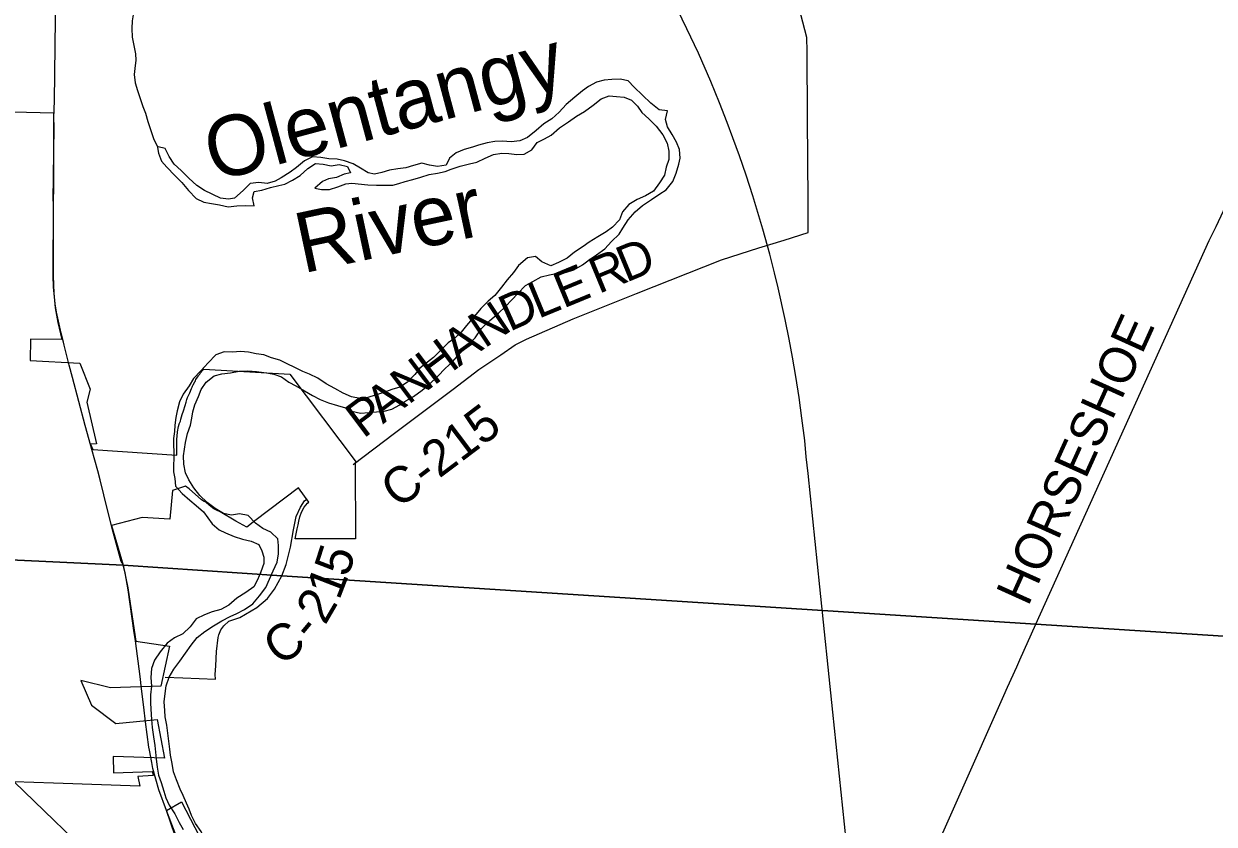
# Model space of a CAD drawing. Extents: x 1674899 to 2057726, y 653888 to 988278.
# Drawn here: x 1808187 to 1818064, y 846092 to 852735 of the extents above; entities that cross this region are included whole.
import ezdxf

# ---------------------------------------------------------------- set-up
doc = ezdxf.new("R2010")
doc.units = 0
for name, color, linetype in [('GM_X_Corporation', 7, 'Continuous'), ('GM_X_County_Road', 7, 'Continuous'), ('GM_X_County_Road_Text', 7, 'Continuous'), ('GM_X_Major_River', 7, 'Continuous'), ('GM_X_Major_River_Text', 7, 'Continuous'), ('GM_X_Rail_Line', 7, 'Continuous'), ('GM_X_Township', 7, 'Continuous'), ('GM_X_US_Route', 7, 'Continuous'), ('SH_Data', 7, 'Continuous')]:
    doc.layers.add(name, color=color, linetype=linetype)

msp = doc.modelspace()

# ---------------------------------------------------------------- linework, layer by layer
at = {"layer": 'GM_X_Corporation'}
for points in [[(1807090.5, 852030.9), (1808433.3, 851997.1), (1808430.6, 850641.2), (1808435.6, 850498.4), (1808448.8, 850376.5), (1808470.4, 850254.7), (1808503.7, 850114.3), (1808242.6, 850117.7), (1808241.4, 849940.9), (1808653.6, 849917.4), (1808736.6, 849703.2), (1808709.5, 849594.5), (1808789.7, 849247.5), (1808740.4, 849246), (1808759.2, 849201.3), (1809456.4, 849153.7), (1809458.3, 849293.9), (1809458.8, 849306.9), (1809459.7, 849321.9), (1809461.3, 849339.8), (1809462.4, 849348.8), (1809462.7, 849349.8), (1809464.3, 849361.6), (1809467.4, 849379.4), (1809470.4, 849393.1), (1809472.4, 849400.8), (1809474.7, 849407.4), (1809476, 849410.7), (1809477.3, 849413.9), (1809480.2, 849420.4), (1809484.2, 849430.6), (1809486.2, 849436.3), (1809491.3, 849453.5), (1809496.8, 849473.8), (1809501.8, 849491.1), (1809511.4, 849521.6), (1809526.6, 849568.1), (1809534.3, 849594.8), (1809537.1, 849604.6), (1809541.3, 849618), (1809544.1, 849626.5), (1809546.1, 849632.1), (1809551.1, 849644.1), (1809559.7, 849662.2), (1809564.6, 849673.2), (1809578.4, 849707.6), (1809583.4, 849719.5), (1809587.6, 849728.6), (1809592.6, 849738.4), (1809606.4, 849763.9), (1809610.9, 849772.8), (1809615.5, 849781.8), (1809621.5, 849792.1), (1809623.1, 849794.6), (1809627.8, 849801.1), (1809636.7, 849812), (1809640.8, 849817.6), (1809646.6, 849825.9), (1809654.2, 849837.6), (1809659.5, 849844.8), (1809665.8, 849852.5), (1809681.3, 849869.6), (1810394.1, 849826.1), (1810944.6, 849097.3), (1810937.2, 849091.7), (1810938.9, 848461.5), (1810439.8, 848460.4), (1810456.3, 848543.1), (1810462.5, 848575.2), (1810468.8, 848607.4), (1810478.5, 848644.1), (1810492.1, 848681.9), (1810514.7, 848723), (1810542, 848756.1), (1810551.8, 848765.3), (1810465.5, 848882.7), (1810104.8, 848611.1), (1810038.5, 848558), (1809945.3, 848607.5), (1809816.7, 848685.3), (1809792.1, 848696.4), (1809763.1, 848710.7), (1809725.8, 848739.6), (1809696.6, 848763.7), (1809685, 848771.5), (1809661.7, 848785.4), (1809559.7, 848874.9), (1809530, 848898.8), (1809421.3, 848861.3), (1809398.5, 848624.8), (1809168.2, 848636.6), (1808913.8, 848570.5), (1809012, 848240.9), (1809051.8, 848052.7), (1809116.6, 847609.9), (1809395.4, 847570.7), (1809324.5, 847237.2), (1808905.8, 847222.5), (1808660.3, 847283.7), (1808750.4, 847078.8), (1808949.9, 846926.5), (1809293.9, 846960.7), (1809355.4, 846639.4), (1808927.8, 846653.4), (1808932.6, 846517.5), (1809251.4, 846528.7), (1809259.5, 846495.6), (1809133.3, 846486.7), (1809148.8, 846407.2), (1808433.2, 846432.2), (1808107.2, 846443.6), (1808850, 845723.9)], [(1809452.7, 845995.8), (1809370.2, 846204.8), (1809494.6, 846276.2), (1809904.5, 845489.7)]]:
    msp.add_lwpolyline(points, dxfattribs=at)
at = {"layer": 'GM_X_County_Road'}
for points in [[(1816452.3, 847455.2), (1816585.7, 847751.3), (1818021.5, 850936.9), (1818080.6, 851051.6), (1818426.4, 851790.7), (1818462.5, 851866.6), (1818600.4, 852026.5), (1818666.6, 852103.2), (1818835.2, 852306.4), (1818894.6, 852378), (1819166, 852831), (1819204.7, 852895.5), (1819487.3, 853403), (1819530.7, 853481.1), (1819699.4, 854255), (1819714.7, 854325.4), (1819939.9, 855786.8), (1819970.6, 855999.9), (1819978.5, 856052.5)], [(1814694.4, 851004.4), (1814694.7, 851266), (1814689.4, 851949.7), (1814688.5, 852505.2), (1814683.1, 852620.4), (1814443.9, 853546.9), (1814428.6, 853618.3), (1814334.6, 854030.1), (1814320.5, 854091.6), (1814317.2, 854102.3)], [(1810919.1, 849077.6), (1811262.7, 849337), (1811751, 849701.5), (1811961.5, 849865), (1812146.5, 849988.4), (1812263.7, 850069.4), (1812359.1, 850118.6), (1812745.4, 850286.5), (1813270.8, 850497.8), (1813977.4, 850776.9), (1814285.7, 850876.9), (1814495.2, 850939.2), (1814694.4, 851004.4)], [(1809806.6, 847662.7), (1809821.3, 847703.6), (1809846.5, 847738.8), (1809889.3, 847776.6), (1809980.5, 847807.3), (1810120.4, 847889.7), (1810210.6, 847966.4), (1810266.1, 848041.2), (1810327.5, 848152), (1810364.3, 848246.6), (1810399.3, 848390.4), (1810424.5, 848536.1), (1810447.8, 848646.8), (1810482.8, 848724.5), (1810515.8, 848776.9), (1810538.1, 848793.3)], [(1809360.2, 847312.3), (1809507.8, 847307.8), (1809776.7, 847295.3), (1809775.2, 847335.4), (1809780.8, 847406.2), (1809787.5, 847525.8), (1809798.7, 847640.7), (1809806.6, 847662.7)], [(1814100.7, 842163.9), (1814760.4, 843649.3), (1815210.3, 844662.2), (1816319.7, 847160.1), (1816350.6, 847229.4), (1816426.4, 847397.7), (1816452.3, 847455.2)]]:
    msp.add_lwpolyline(points, dxfattribs=at)
at = {"layer": 'GM_X_Major_River'}
for points in [[(1809101.6, 852887.5), (1809097.5, 852877.5), (1809097.1, 852827.5), (1809086.6, 852759.4), (1809084, 852695.4), (1809085.5, 852625.3), (1809098.9, 852555.1), (1809114.4, 852486.9), (1809117.9, 852432.8), (1809109.4, 852364.7), (1809103, 852314.7), (1809110.4, 852246.6), (1809131.9, 852182.3), (1809174.8, 852049.8), (1809198.4, 851993.5), (1809217.8, 851923.3), (1809241.2, 851851), (1809262.7, 851782.8), (1809296.1, 851714.4)], [(1812126.9, 850332.7), (1812185.3, 850388.3), (1812235.8, 850444), (1812286.2, 850495.7), (1812348.7, 850563.3), (1812411, 850596.9), (1812481.3, 850634.4), (1812549.4, 850651.9), (1812615.5, 850665.4), (1812689.6, 850674.8), (1812749.8, 850692.4), (1812822.1, 850733.9), (1812888.5, 850783.4), (1812938.8, 850817.1), (1813009.2, 850866.7), (1813063.7, 850928.3), (1813126.1, 850987.9), (1813156.5, 851039.8), (1813203.1, 851107.5), (1813259.6, 851175.2), (1813322.1, 851226.7), (1813394.5, 851278.3), (1813464.8, 851323.8), (1813517.1, 851357.4), (1813573.7, 851427.1), (1813600.2, 851495), (1813622.8, 851568.9), (1813633.2, 851620.9), (1813627.8, 851691), (1813602.3, 851753.3), (1813566.8, 851815.7), (1813527.3, 851880.1), (1813511.8, 851942.3), (1813528.4, 852014.2), (1813458.5, 852020.8), (1813388.9, 852077.4), (1813319.5, 852144), (1813252, 852210.7), (1813202.4, 852261.1), (1813134.5, 852275.6), (1813066.5, 852274.2), (1813002.5, 852268.7), (1812938.3, 852251.1), (1812872, 852213.6), (1812821.8, 852179.9), (1812759.3, 852126.3), (1812686.9, 852064.8), (1812630.4, 852003.2), (1812567.9, 851947.5), (1812501.6, 851906), (1812439.1, 851848.4), (1812366.7, 851792.9), (1812302.4, 851763.3), (1812232.4, 851755.8), (1812158.4, 851760.4), (1812094.4, 851758.9), (1812032.3, 851747.4), (1811960.2, 851727.9), (1811910, 851712.3), (1811839.9, 851690.8), (1811775.7, 851665.2), (1811719.3, 851619.6), (1811690.8, 851561.8), (1811620.7, 851550.3), (1811554.8, 851560.8), (1811491, 851579.3), (1811420.8, 851557.8), (1811356.7, 851540.3), (1811290.6, 851532.8), (1811222.5, 851521.3), (1811158.3, 851501.8), (1811096.2, 851486.2), (1811044.3, 851498.6), (1810980.6, 851537.2), (1810920.9, 851571.7), (1810849.1, 851598.3), (1810787.3, 851612.8), (1810719.3, 851615.3), (1810651.4, 851625.8), (1810583.4, 851630.4), (1810515.1, 851596.8), (1810448.7, 851541.3), (1810398.4, 851503.6), (1810322, 851456.1), (1810271.8, 851428.5), (1810205.6, 851409), (1810137.7, 851417.5), (1810065.6, 851410.1), (1810007.2, 851352.4), (1809936.7, 851288.9), (1809886.6, 851279.3), (1809818.7, 851287.8), (1809687.2, 851352.9), (1809623.5, 851393.4), (1809558, 851454), (1809492.5, 851516.6), (1809434.9, 851569.1), (1809393.4, 851633.5), (1809360, 851699.9), (1809301.3, 851713.5), (1809296.1, 851714.4)], [(1809296.1, 851714.4), (1809295.6, 851709.9), (1809303.7, 851660.3), (1809331.1, 851596), (1809374.7, 851545.6), (1809440.2, 851477), (1809499.7, 851418.4), (1809555.2, 851351.9), (1809618.6, 851285.3), (1809682.4, 851254.8), (1809744.3, 851244.3), (1809812.2, 851231.8), (1809884.1, 851217.2), (1809954.1, 851224.7), (1810026.2, 851228.1), (1810098.1, 851223.5), (1810084.7, 851291.8), (1810099.1, 851343.7), (1810163.2, 851355.2), (1810235.4, 851376.7), (1810303.5, 851394.2), (1810353.6, 851403.8), (1810415.9, 851437.4), (1810480.2, 851474.9), (1810544.6, 851534.5), (1810607, 851576.1), (1810670.9, 851569.6), (1810736.8, 851555.1), (1810804.9, 851566.6), (1810872.8, 851552), (1810898.3, 851497.8), (1810846.2, 851486.2), (1810782, 851458.6), (1810715.9, 851449.1), (1810665.8, 851427.4), (1810603.3, 851369.9), (1810657.2, 851359.4), (1810723.2, 851360.9), (1810793.4, 851382.4), (1810859.6, 851405.9), (1810909.6, 851411.5), (1811041.5, 851398.5), (1811113.5, 851396), (1811179.5, 851395.5), (1811249.5, 851394.9), (1811299.6, 851410.5), (1811351.7, 851426.2), (1811415.9, 851443.7), (1811482, 851461.2), (1811550.2, 851484.7), (1811620.3, 851496.2), (1811682.4, 851509.7), (1811732.5, 851527.4), (1811806.7, 851552.8), (1811884.9, 851572.3), (1811947, 851587.8), (1812015.3, 851621.3), (1812085.5, 851650.8), (1812153.6, 851660.3), (1812211.6, 851659.9), (1812279.5, 851651.3), (1812339.5, 851652.9), (1812401.8, 851690.5), (1812446.3, 851750.2), (1812506.6, 851781.8), (1812562.8, 851811.4), (1812631.3, 851873), (1812707.7, 851920.4), (1812772.1, 851968), (1812840.4, 852007.5), (1812910.8, 852061.1), (1812977.2, 852112.6), (1813043.4, 852136.2), (1813105.4, 852131.7), (1813169.3, 852127.2), (1813229.1, 852100.7), (1813280.7, 852052.2), (1813314.3, 851999.9), (1813373.9, 851947.3), (1813433.4, 851884.8), (1813488.8, 851814.3), (1813526.2, 851745.9), (1813539.7, 851677.7), (1813539.1, 851609.6), (1813518.6, 851545.7), (1813504.1, 851477.7), (1813461.6, 851415.9), (1813413, 851346.2), (1813346.7, 851308.7), (1813276.5, 851277.2), (1813206.1, 851235.6), (1813155.7, 851175.9), (1813129.1, 851108.1), (1813070.6, 851046.4), (1813018.3, 851008.8), (1812950, 850967.2), (1812877.6, 850923.7), (1812827.3, 850886.1), (1812756.9, 850838.5), (1812694.5, 850788.9), (1812624.3, 850755.4)], [(1812624.3, 850755.4), (1812560, 850725.9), (1812486.3, 850760.5), (1812432.7, 850803), (1812366.6, 850793.5), (1812292.1, 850730), (1812251.6, 850670.2), (1812197.1, 850610.5), (1812150.6, 850548.8), (1812096.1, 850481.1), (1812039.7, 850433.5), (1811979.2, 850371.9), (1811926.7, 850308.2), (1811860.1, 850230.6), (1811817.6, 850176.8), (1811761.2, 850123.2), (1811708.9, 850087.5), (1811652.5, 850031.9), (1811587.9, 849964.3), (1811535.6, 849926.7), (1811473.2, 849877.1), (1811432.8, 849825.3), (1811372.3, 849761.7), (1811308, 849718.1), (1811239.8, 849700.6), (1811167.6, 849673.1), (1811101.4, 849653.6), (1811041.3, 849634), (1810979.2, 849626.5), (1810907.3, 849639.1), (1810837.6, 849669.7), (1810767.9, 849708.3), (1810696.2, 849746.9), (1810626.6, 849793.5), (1810556.9, 849828.1), (1810503, 849850.5), (1810437.3, 849883.1), (1810373.5, 849911.6), (1810311.8, 849942.1), (1810243.9, 849962.7), (1810178.2, 849987.2), (1810114.2, 849995.7), (1810052.3, 850010.2), (1809984.4, 850014.8), (1809918.3, 850009.2), (1809850.4, 850013.8), (1809780.2, 849988.3), (1809717.6, 849920.7), (1809657.1, 849855), (1809596.6, 849791.4), (1809558.1, 849731.6), (1809509.5, 849661.9), (1809479, 849598.1), (1809460.4, 849524.1), (1809448, 849468.1), (1809441.5, 849404.1), (1809439, 849352), (1809428.6, 849292), (1809430.1, 849239.9), (1809431.7, 849183.8), (1809430.3, 849015.6), (1809439.9, 848961.5), (1809445.4, 848897.3), (1809500.9, 848836.8), (1809564.5, 848780.2), (1809616.1, 848735.8), (1809679.7, 848685.2), (1809750.9, 848584.5), (1809808.5, 848536), (1809860.3, 848509.6), (1809932, 848481), (1810001.9, 848456.4), (1810073.7, 848441.8), (1810137.5, 848413.3), (1810163.1, 848361), (1810178.6, 848306.8), (1810178.2, 848254.8), (1810153.7, 848186.8), (1810125.1, 848119), (1810094.7, 848063.1), (1810028.3, 848015.6), (1809953.9, 847968.1), (1809887.5, 847908.5), (1809823.2, 847872.9), (1809751, 847855.5), (1809686.8, 847829.9), (1809618.6, 847796.4), (1809568, 847728.7), (1809505.6, 847673.1), (1809437.3, 847639.6), (1809377, 847594), (1809318.4, 847522.3), (1809271.8, 847452.6), (1809247.3, 847382.7), (1809240.7, 847310.6), (1809248.1, 847238.5), (1809239.5, 847166.4), (1809239, 847098.3), (1809240.6, 847046.2), (1809245.9, 846960.1), (1809253.4, 846893.9)], [(1809611, 846097.9), (1809579.6, 846164.3), (1809560, 846216.5), (1809536.4, 846266.8), (1809508.9, 846331.1), (1809485.3, 846383.3), (1809453.9, 846459.7), (1809430.4, 846526), (1809417, 846596.2), (1809405.5, 846664.4), (1809397.9, 846714.5), (1809383, 846846.8), (1809373.5, 846913), (1809360.1, 846983.2), (1809356.5, 847035.3), (1809351.1, 847107.5), (1809359.6, 847175.5), (1809368.1, 847239.5), (1809392.7, 847311.4), (1809431.2, 847377.2), (1809481.8, 847444.9), (1809530.3, 847510.7), (1809576.8, 847576.4), (1809625.3, 847642.1), (1809689.7, 847691.7), (1809760.1, 847737.2), (1809830.4, 847780.8), (1809900.7, 847816.2), (1809954.9, 847841.9), (1810017.2, 847873.4), (1810087.6, 847921), (1810144.1, 847986.6), (1810194.6, 848056.3), (1810225.2, 848124.2), (1810255.7, 848194.1), (1810288.3, 848267.9), (1810300.9, 848335.9), (1810301.4, 848406), (1810293.9, 848460.2), (1810236.3, 848516.7), (1810170.6, 848547.2), (1810110.9, 848589.8), (1810049.4, 848654.3), (1809977.5, 848666.9), (1809911.4, 848655.4), (1809845.6, 848669.9), (1809775.9, 848712.5), (1809708.3, 848763.1), (1809648.8, 848819.7), (1809597.3, 848884.1), (1809555.8, 848950.5), (1809530.3, 849006.8), (1809514.9, 849079), (1809513.4, 849149.2), (1809519.9, 849205.2), (1809530.3, 849261.2), (1809546.9, 849335.2), (1809569.5, 849403.1), (1809581.9, 849463.1), (1809590.4, 849515.1), (1809606.8, 849573), (1809637.4, 849642.9), (1809659.8, 849698.8), (1809700.3, 849760.6), (1809766.8, 849814.1), (1809830.9, 849829.7), (1809903, 849839.1), (1809975.1, 849852.6), (1810047.1, 849856), (1810119, 849849.5), (1810201, 849838.8), (1810260.9, 849826.3), (1810326.7, 849805.8), (1810386.3, 849761.3), (1810444.1, 849730.8), (1810515.7, 849688.2), (1810581.4, 849649.6), (1810647.2, 849617.1), (1810714.9, 849588.5), (1810788.8, 849567.9), (1810856.6, 849547.4), (1810908.4, 849520.9), (1810982.2, 849504.3), (1811050.3, 849507.8), (1811114.3, 849513.3), (1811176.4, 849518.9), (1811240.5, 849536.4), (1811306.8, 849571.9), (1811357, 849605.6), (1811421.3, 849643.1), (1811491.8, 849694.7), (1811552.1, 849742.3), (1811622.7, 849809.8), (1811683.2, 849875.4), (1811745.6, 849929), (1811802.2, 849996.7), (1811862.7, 850060.3), (1811931.3, 850129.9), (1811983.9, 850205.6), (1812054.4, 850273.2), (1812126.9, 850332.7)], [(1809253.4, 846893.9), (1809264.8, 846815.7), (1809274.2, 846743.5), (1809285.3, 846635.3), (1809294.8, 846565.1), (1809304.2, 846498.9), (1809325.7, 846436.7), (1809349.2, 846366.4), (1809366.7, 846310.2), (1809394.2, 846249.8), (1809439.7, 846177.4), (1809477.1, 846107), (1809510.6, 846046.7)], [(1810152.2, 844729.7), (1810130.7, 844799.9), (1810115.4, 844878.2), (1810101.8, 844932.4), (1810076.3, 845002.7), (1810048.9, 845069), (1810031.3, 845123.2), (1810013.9, 845195.5), (1810000.3, 845247.6), (1809988.7, 845297.8), (1809977.1, 845350), (1809967.7, 845424.2), (1809962.1, 845478.3), (1809940.6, 845544.6), (1809907.2, 845614.9), (1809861.7, 845675.4), (1809804.2, 845739.9), (1809768.6, 845790.3), (1809735.1, 845858.6), (1809713.5, 845908.9), (1809690, 845961.1), (1809658.5, 846031.5), (1809611, 846097.9)]]:
    msp.add_lwpolyline(points, dxfattribs=at)
at = {"layer": 'GM_X_Rail_Line'}
msp.add_lwpolyline([(1815024.3, 845825.8), (1814900, 847022.3), (1814792.8, 848062.2), (1814694.8, 849003.1), (1814679.6, 849140.1), (1814666.5, 849276.5), (1814642.8, 849460.9), (1814619.5, 849632.7), (1814592.7, 849806.6), (1814564.9, 849967.3), (1814536.6, 850116.8), (1814503.3, 850282.1), (1814445.7, 850543.8), (1814415.4, 850667.6), (1814376, 850823.7), (1814318.3, 851031.4), (1814278.4, 851168.4), (1814235.5, 851307.8), (1814180.4, 851477.6), (1814124.8, 851639.3), (1814071.3, 851788.9), (1814023.2, 851916.2), (1813959.6, 852078.9), (1813886.8, 852257.3), (1813784.2, 852491.3), (1813688.7, 852694.9), (1813610.9, 852854.1)], dxfattribs=at)
at = {"layer": 'GM_X_Township'}
msp.add_lwpolyline([(1794528.5, 849264.7), (1794738.4, 851729.1), (1795089.6, 856488.1), (1795246.9, 858498.9), (1795572.8, 862604.1), (1796250.1, 870608.5), (1796650.9, 875449.1), (1801483.5, 875120.1), (1808583.7, 874680.4), (1818820.4, 874127.4), (1822582.6, 873900.6), (1822382.4, 871012.6), (1821955.8, 864281.1), (1821820, 862137.7), (1821742.6, 860915.1), (1821306.3, 853784), (1821203.9, 851968.5), (1820950.3, 847471.9), (1816585.7, 847751.2), (1810327.5, 848152), (1809012, 848240.9), (1805038.1, 848429.5), (1801113.4, 848727.8), (1800736.4, 848740)], close=True, dxfattribs=at)
msp.add_lwpolyline([(1805038.1, 848429.5), (1809012, 848240.9), (1810327.5, 848152), (1816585.7, 847751.2), (1820950.3, 847471.9), (1820789.2, 844649.9), (1820410.6, 838018.1), (1820357.1, 837080.2), (1820273.9, 835622.7), (1820182.4, 834020.7), (1820000.3, 830811.8), (1819973.4, 830336.5), (1819571.4, 823252.9), (1819402.7, 820561.6), (1817422, 820661), (1816436.6, 820719.4), (1811976.8, 820983.9), (1811438.7, 820997.6), (1810371.4, 821058.5), (1808814, 821112.9), (1806011.6, 821223.2)], dxfattribs=at)
at = {"layer": 'GM_X_US_Route'}
for points in [[(1808436.7, 851953.6), (1808441.2, 852096.6), (1808473.9, 854817), (1808492.7, 856391.6), (1808500.9, 857013.5), (1808509.5, 857555.2), (1808510.5, 857627.6)], [(1808515.9, 850092.2), (1808496.1, 850167.3), (1808458.7, 850340.7), (1808447.9, 850410.8), (1808433.9, 850552), (1808430.6, 850641.2), (1808432.6, 851249.2), (1808431.5, 851273.4), (1808433.2, 851468.5), (1808436.7, 851667.7), (1808439.2, 851882.5), (1808436.7, 851953.6)], [(1808563.1, 849901.2), (1808563.1, 849901.2), (1808522.2, 850068.4), (1808515.9, 850092.2)], [(1808697.2, 849401.4), (1808591.8, 849800.4), (1808563.1, 849901.2)], [(1808752, 849201.8), (1808702.6, 849380.8), (1808697.2, 849401.4)], [(1808820.8, 848950.2), (1808802.8, 849023.6), (1808752, 849201.8)], [(1808920.8, 848545), (1808913.8, 848570.5), (1808882, 848700.2), (1808820.8, 848950.2)], [(1809104.2, 847680.7), (1809054.1, 848035.9), (1809027.1, 848178.7), (1809012, 848240.9), (1809010.4, 848249), (1808995, 848272.1), (1808920.8, 848545)], [(1809163.9, 847216.4), (1809151.8, 847318.6), (1809113.8, 847612.6), (1809104.2, 847680.7)], [(1809182.2, 847063.1), (1809163.9, 847216.4)], [(1809229.5, 846706.2), (1809224.6, 846732), (1809196.6, 846941.2), (1809182.2, 847063.1)], [(1809248.9, 846605.1), (1809229.5, 846706.2)], [(1809258.5, 846554.6), (1809248.9, 846605.1)], [(1809486.2, 845871.7), (1809442.3, 845994.9), (1809370.2, 846204.8), (1809307.3, 846377.8), (1809258.9, 846552.8), (1809258.5, 846554.6)]]:
    msp.add_lwpolyline(points, dxfattribs=at)
at = {"layer": 'SH_Data'}
for points in [[(1808436.7, 851953.6), (1808441.2, 852096.6), (1808473.9, 854817), (1808492.7, 856391.6), (1808500.9, 857013.5), (1808509.5, 857555.2), (1808510.5, 857627.6)], [(1808515.9, 850092.2), (1808496.1, 850167.3), (1808458.7, 850340.7), (1808447.9, 850410.8), (1808433.9, 850552), (1808430.6, 850641.2), (1808432.6, 851249.2), (1808431.5, 851273.4), (1808433.2, 851468.5), (1808436.7, 851667.7), (1808439.2, 851882.5), (1808436.7, 851953.6)], [(1808563.1, 849901.2), (1808563.1, 849901.2), (1808522.2, 850068.4), (1808515.9, 850092.2)], [(1808697.2, 849401.4), (1808591.8, 849800.4), (1808563.1, 849901.2)], [(1808752, 849201.8), (1808702.6, 849380.8), (1808697.2, 849401.4)], [(1808820.8, 848950.2), (1808802.8, 849023.6), (1808752, 849201.8)], [(1808920.8, 848545), (1808913.8, 848570.5), (1808882, 848700.2), (1808820.8, 848950.2)], [(1809104.2, 847680.7), (1809054.1, 848035.9), (1809027.1, 848178.7), (1809012, 848240.9), (1809010.4, 848249), (1808995, 848272.1), (1808920.8, 848545)], [(1809163.9, 847216.4), (1809151.8, 847318.6), (1809113.8, 847612.6), (1809104.2, 847680.7)], [(1809182.2, 847063.1), (1809163.9, 847216.4)], [(1809229.5, 846706.2), (1809224.6, 846732), (1809196.6, 846941.2), (1809182.2, 847063.1)], [(1809248.9, 846605.1), (1809229.5, 846706.2)], [(1809258.5, 846554.6), (1809248.9, 846605.1)], [(1809486.2, 845871.7), (1809442.3, 845994.9), (1809370.2, 846204.8), (1809307.3, 846377.8), (1809258.9, 846552.8), (1809258.5, 846554.6)]]:
    msp.add_lwpolyline(points, dxfattribs=at)

# ---------------------------------------------------------------- texts
at = {"layer": 'GM_X_County_Road_Text'}
for s, rotation, p in [('D', 22.42848, (1813184.4, 850585.3)), ('R', 22.43087, (1812956.6, 850491.3)), ('E', 22.42536, (1812663.7, 850370.4)), ('D', 24.15333, (1812217.7, 850177.6)), ('L', 22.46195, (1812456.4, 850284.7)), ('N', 33.74867, (1812009.8, 850037.4)), ('HORSESHOE', 65.68168, (1816520, 847892.3)), ('A', 35.79303, (1811797.9, 849884.6)), ('H', 36.87936, (1811588, 849727)), ('N', 36.96186, (1811377.2, 849568.4)), ('A', 36.95937, (1811166.2, 849409.6)), ('P', 36.95875, (1811004.4, 849287.9)), ('C-215', 36.97949, (1811295.9, 848703.3)), ('5', 72.15927, (1810876.2, 848133.9)), ('1', 68.88103, (1810803.4, 847943.8)), ('2', 59.76015, (1810687.7, 847737.2)), ('C', 34.96532, (1810311.6, 847397.9)), ('-', 50.19991, (1810577.5, 847597.9))]:
    msp.add_text(s, height=300, rotation=rotation, dxfattribs=at).set_placement(p)
at = {"layer": 'GM_X_Major_River_Text'}
for s, rotation, p in [('Olentangy', 15.01858, (1809765.4, 851422.9)), ('River', 12.01898, (1810501.4, 850662.7))]:
    msp.add_text(s, height=500, rotation=rotation, dxfattribs=at).set_placement(p)

doc.saveas('drawing.dxf')
